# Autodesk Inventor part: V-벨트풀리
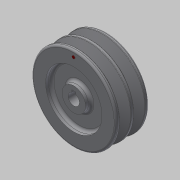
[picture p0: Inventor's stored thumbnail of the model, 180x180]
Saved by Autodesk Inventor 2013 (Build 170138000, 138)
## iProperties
Created: 2016-08
Part Number: V-벨트풀리
Material: 알루미늄 6061
Document SubType Name: Modeling
Designer: mduedu
Density: 2.71 g/cm^3
Mass: 380.112 g
Surface Area: 333.15 cm^2
Volume: 140.263 cm^3
Author: mduedu
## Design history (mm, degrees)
sketch "스케치1"
  geometry: L1 (0, 17.5)-(0, -17.5); L2 (0, -17.5)-(45, -17.5); L3 (45, -17.5)-(45, 17.5); L4 (45, 17.5)-(0, 17.5); L5 (45, -1.524)-(32.5, -5.346); L6 (32.5, -5.346)-(32.5, -9.654); L7 (32.5, -9.654)-(45, -13.476); L8 (45, 13.476)-(32.5, 9.654); L9 (32.5, 9.654)-(32.5, 5.346); L10 (32.5, 5.346)-(45, 1.524); L11 (40.5, 17.5)-(40.5, -17.5); L12 (45, -7.5)-(0, -7.5); L13 (45, 7.5)-(0, 7.5); 8 further points
  constraints: 26 end point, 20 point on line, 6 perpendicular, 3 equal length, 3 midpoint, 2 collinear, 1 coincident, 1 horizontal, 1 vertical
  dimensions: "d43" = 90 diameter of L3 L1; "d45" = 34 deg angle of L7 L5; "d47" = 34 deg angle of L8 L10; "d49" = 9.2 distance of point (40.5, -12.1) point (40.5, -2.9); "d50" = 9.2 distance of point (40.5, 12.1) point (40.5, 2.9) (derived); "d51" = 10 distance between parallel lines of L12 L2; "d52" = 10 distance between parallel lines of L13 L4; "d53" = 15 distance between parallel lines of L12 L13; "d54" = 4.5 distance between parallel lines of L11 L3; "d55" = 8 distance between parallel lines of L6 L11
revolve "회전1" sketch "스케치1" stored, may be unused: angle "d8" = 90 deg
sketch "스케치2"
  geometry: L1 (-2, 0)-(2, 0); L2 (2, 0)-(2, 7.8); L3 (2, 7.8)-(-2, 7.8); L4 (-2, 7.8)-(-2, 0); C1 r 6 at (0, 0); 3 further points
  constraints: 8 end point, 3 coincident, 2 parallel, 1 centre point, 1 horizontal, 1 midpoint, 1 perpendicular
  dimensions: "d9" = 12 diameter of C1; "d11" = 4 distance of L2.end L3.end; "d12" = 7.8 distance of L1.end L2.end
extrude "돌출1" cut sketch "스케치2" stored distance "d13" = 10; taper "d14" = 0 deg
sketch "스케치4"
  geometry: C1 r 30 at (0, 0); C2 r 12.5 at (0, 0); 2 further points
  constraints: 3 coincident, 2 centre point
  dimensions: "d30" = 60 diameter of C1; "d31" = 25 diameter of C2
extrude "돌출2" cut sketch "스케치4" distance "d32" = 6; taper "d33" = 0 deg
fillet "모깎기6" dims "d34" = 3
fillet "모깎기8" dims "d56" = 0.5, "d57" = 1, "d58" = 2
chamfer "모따기1" distance "d26" = 0.5; stored, may be unused: second distance "d27" = 2, angle "d28" = 45 deg
sketch "스케치5" dims "d38" = 78
  geometry: C1 r 1.5 at (0, 39); 3 further points
  constraints: 2 coincident, 2 vertical alignment, 1 centre point, 2 other
  dimensions: "d40" = 3 diameter of C1
extrude "돌출3" join sketch "스케치5" distance "d41" = 0.5; taper "d42" = 0 deg
node "솔리드1"
mirror "대칭2"
